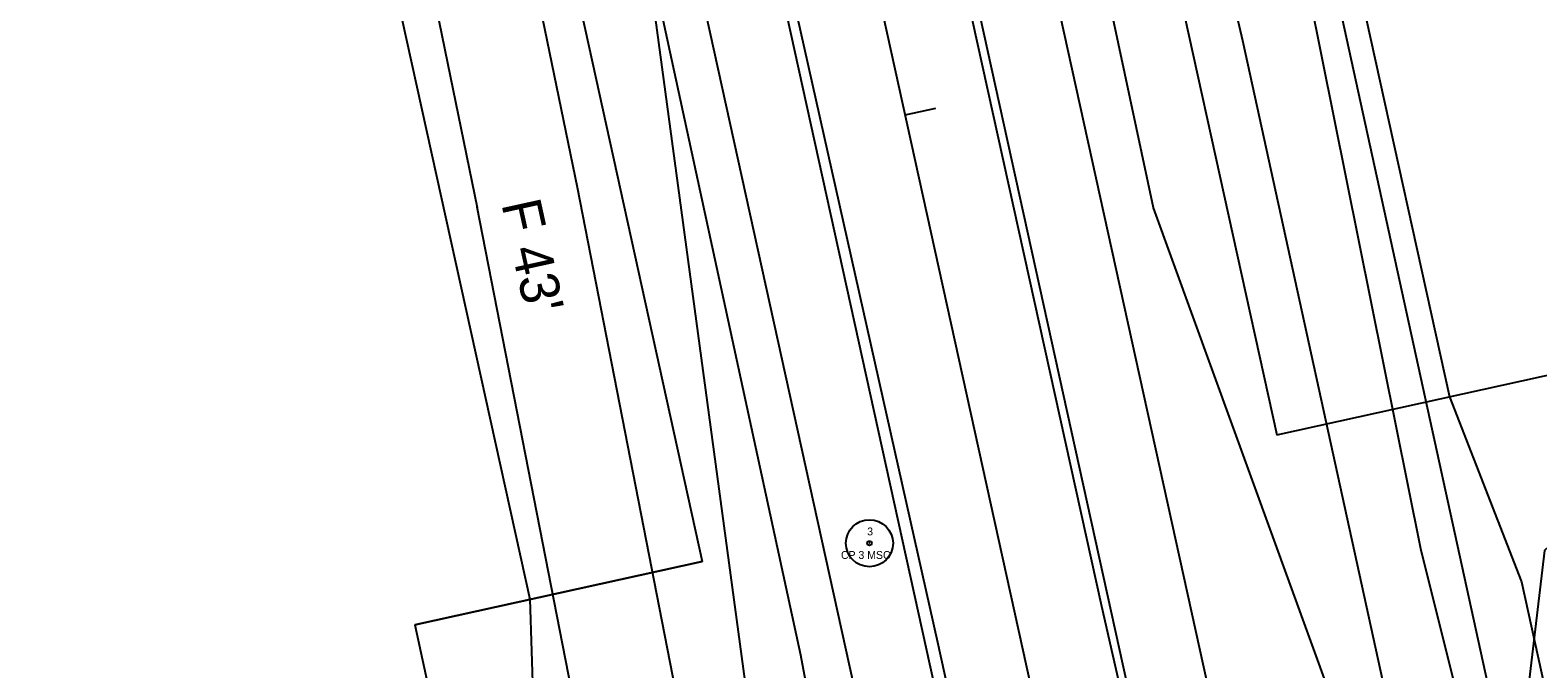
# Model space of a CAD drawing. Extents: x 2519952 to 2531965, y 848341 to 887632.
# Drawn here: x 2524114.7 to 2524306.9, y 857170.6 to 857252 of the extents above; entities that cross this region are included whole.
import ezdxf

# ---------------------------------------------------------------- set-up
doc = ezdxf.new("R2010")
doc.units = 0
for name, color, linetype in [('RD_EV_JW', 7, 'Continuous'), ('RD_EX_DV_Prop', 7, 'Continuous'), ('RD_EX_Misc', 7, 'Continuous'), ('RD_EX_Road', 7, 'Continuous'), ('RD_EX_RW', 7, 'Continuous'), ('RD_EX_VEG', 7, 'Continuous'), ('RD_HC_Cl', 7, 'Continuous'), ('RD_HC_Data', 7, 'Continuous'), ('RD_HC_Data_Tic', 7, 'Continuous'), ('RD_HC_txCode', 7, 'Continuous'), ('RD_PD_BCA', 7, 'Continuous'), ('RD_PD_CstnLmt', 7, 'Continuous'), ('RD_PD_DR_ErosCtrl', 7, 'Continuous'), ('RD_PD_Final_TrvlWay', 7, 'Continuous'), ('RD_PD_GR', 7, 'Continuous'), ('RD_PD_RW', 7, 'Continuous'), ('RD_SMD_Locator', 7, 'Continuous')]:
    doc.layers.add(name, color=color, linetype=linetype)

msp = doc.modelspace()

# ---------------------------------------------------------------- linework, layer by layer
at = {"layer": 'RD_EV_JW'}
for points in [[(2524241.25, 857057.8), (2524220.66, 857072.8), (2524210.63, 857133.54), (2524190.68, 857281.24), (2524178.18, 857334.96), (2524155.01, 857422.39), (2524137.68, 857488.01), (2524120.9, 857534.64), (2524063.74, 857650.68), (2524019.29, 857616.94), (2523974.51, 857570.75)], [(2524241.25, 857057.8), (2524288.29, 857072.98), (2524302, 857102.41), (2524282.93, 857160.32), (2524257.89, 857229.33), (2524228.28, 857368.09), (2524210.76, 857440.65), (2524188.72, 857541.07), (2524178.8, 857585.79), (2524207.91, 857589.59), (2524237.38, 857595.52)]]:
    msp.add_lwpolyline(points, dxfattribs=at)
at = {"layer": 'RD_EX_DV_Prop'}
for p, q in [((2524157.87, 857726.04), (2524273.61, 857200.43)), ((2524150.8, 857409.4), (2524200.37, 857184.3)), ((2524273.61, 857200.43), (2524310.23, 857208.49)), ((2524200.37, 857184.3), (2524163.74, 857176.23)), ((2524163.74, 857176.23), (2524228.26, 856883.25))]:
    msp.add_line(p, q, dxfattribs=at)
at = {"layer": 'RD_EX_Misc'}
msp.add_lwpolyline([(2524546.39, 857089.12), (2524517.38, 857137.92), (2524538.03, 857176.84), (2524519.61, 857206.94), (2524513, 857216.34), (2524463.61, 857251.75), (2524420.32, 857237.04), (2524384.22, 857230.02), (2524354.94, 857196.44), (2524330.04, 857206.28), (2524307.73, 857185.7), (2524301.47, 857133.05)], dxfattribs=at)
at = {"layer": 'RD_EX_Road'}
for p, q in [((2524251.32, 857178.56), (2524231.43, 857268.69)), ((2524230.4, 857173.95), (2524210.1, 857264.4)), ((2524272.86, 857083.08), (2524251.32, 857178.56)), ((2524251.66, 857078.33), (2524230.4, 857173.95))]:
    msp.add_line(p, q, dxfattribs=at)
at = {"layer": 'RD_EX_RW'}
for p, q in [((2524157.87, 857726.04), (2524273.61, 857200.42)), ((2524150.8, 857409.4), (2524200.37, 857184.3)), ((2524273.61, 857200.42), (2524310.23, 857208.49)), ((2524163.74, 857176.23), (2524200.37, 857184.3)), ((2524163.74, 857176.23), (2524228.26, 856883.25))]:
    msp.add_line(p, q, dxfattribs=at)
at = {"layer": 'RD_EX_VEG'}
for points in [[(2524305.71, 857130.78), (2524291.95, 857185.88), (2524213.1, 857577.99), (2524167.19, 857800.01)], [(2524229.89, 857081.83), (2524212.94, 857172.34), (2524171.7, 857362.72), (2524119.6, 857524.81)]]:
    msp.add_lwpolyline(points, dxfattribs=at)
at = {"layer": 'RD_HC_Cl'}
msp.add_line((2524121.25, 857717.97), (2524677.84, 855190.33), dxfattribs=at)
at = {"layer": 'RD_HC_Data'}
for radius in [3, 0.282]:
    msp.add_circle((2524221.69, 857186.61), radius, dxfattribs=at)
at = {"layer": 'RD_HC_Data_Tic'}
msp.add_line((2524226.24, 857241.19), (2524230.14, 857242.05), dxfattribs=at)
at = {"layer": 'RD_PD_BCA'}
for p, q in [((2524295.59, 857205.26), (2524304.78, 857181.69)), ((2524304.78, 857181.69), (2524310.13, 857157.24)), ((2524178.39, 857179.46), (2524179.27, 857154.05))]:
    msp.add_line(p, q, dxfattribs=at)
at = {"layer": 'RD_PD_CstnLmt'}
for p, q in [((2524246.67, 857348.09), (2524269.22, 857250.66)), ((2524164.34, 857329.96), (2524184.43, 857231.99)), ((2524269.22, 857250.66), (2524290.59, 857152.97)), ((2524184.43, 857231.99), (2524203.59, 857133.81))]:
    msp.add_line(p, q, dxfattribs=at)
at = {"layer": 'RD_PD_DR_ErosCtrl'}
for p, q in [((2524151.61, 857327.35), (2524171.7, 857229.37)), ((2524281.92, 857253.43), (2524303.29, 857155.74)), ((2524171.67, 857229.49), (2524190.84, 857131.32))]:
    msp.add_line(p, q, dxfattribs=at)
at = {"layer": 'RD_PD_Final_TrvlWay'}
for p, q in [((2524221.83, 857317.02), (2524496.02, 856071.85)), ((2524198.39, 857311.86), (2524472.58, 856066.69))]:
    msp.add_line(p, q, dxfattribs=at)
at = {"layer": 'RD_PD_GR'}
for p, q in [((2524222.18, 857361.9), (2524270.57, 857142.16)), ((2524227.6, 857132.7), (2524179.21, 857352.43))]:
    msp.add_line(p, q, dxfattribs=at)
at = {"layer": 'RD_PD_RW'}
for p, q in [((2524247.2, 857425), (2524295.59, 857205.26)), ((2524130.01, 857399.19), (2524178.39, 857179.46))]:
    msp.add_line(p, q, dxfattribs=at)
at = {"layer": 'RD_SMD_Locator'}
for centre in [(2524257.89, 857229.33), (2524221.69, 857186.61), (2524291.95, 857185.88), (2524251.32, 857178.56), (2524230.4, 857173.95), (2524212.94, 857172.34)]:
    msp.add_circle(centre, 0.001, dxfattribs=at)

# ---------------------------------------------------------------- texts
at = {"layer": 'RD_HC_txCode'}
for s, p in [('3', (2524221.4, 857187.61)), ('CP 3 MSC', (2524218.06, 857184.61))]:
    msp.add_text(s, height=1, dxfattribs=at).set_placement(p)
at = {"layer": 'RD_PD_CstnLmt'}
msp.add_text("F 43'", height=5, rotation=282.4185, dxfattribs=at).set_placement((2524174.77, 857229.86))

doc.saveas('drawing.dxf')
